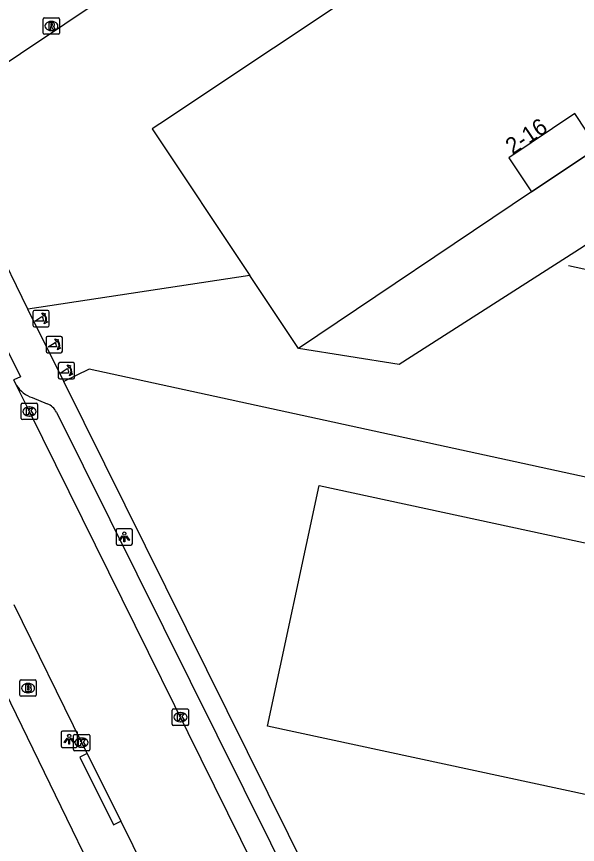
# Model space of a CAD drawing. Extents: x 161354 to 161876, y 382161 to 382804.
# Drawn here: x 161440.8 to 161475, y 382456.1 to 382506.5 of the extents above; entities that cross this region are included whole.
import ezdxf

# ---------------------------------------------------------------- set-up
doc = ezdxf.new("R2010")
doc.units = 0
for name, color, linetype in [('IMGEO_Brandkraan', 7, 'Continuous'), ('IMGEO_Kolk', 7, 'Continuous'), ('IMGEO_Lichtpunt', 7, 'Continuous'), ('IMGEO_Lijnafwatering', 7, 'Continuous'), ('IMGEO_Pand', 7, 'Continuous'), ('IMGEO_Pand_nummerreeks', 7, 'Continuous'), ('IMGEO_Pand_overbouw', 7, 'Continuous'), ('IMGEO_Poller', 7, 'Continuous'), ('IMGEO_Rijbaan_lokaal_open', 7, 'Continuous'), ('IMGEO_Rioolput', 7, 'Continuous'), ('IMGEO_Voetpad_open', 7, 'Continuous')]:
    doc.layers.add(name, color=color, linetype=linetype)

msp = doc.modelspace()

# ---------------------------------------------------------------- linework, layer by layer
at = {"layer": 'IMGEO_Brandkraan'}
for p, q in [((161440.964, 382465.171), (161440.964, 382466.023)), ((161441.039, 382466.097), (161441.891, 382466.097)), ((161441.965, 382466.023), (161441.965, 382465.171)), ((161441.452, 382465.877), (161441.477, 382465.877)), ((161441.891, 382465.097), (161441.039, 382465.097)), ((161441.475, 382465.317), (161441.45, 382465.317))]:
    msp.add_line(p, q, dxfattribs=at)
for points in [[(161440.964, 382465.171), (161440.964, 382466.023)], [(161441.039, 382466.097), (161441.891, 382466.097)], [(161441.965, 382466.023), (161441.965, 382465.171)], [(161441.312, 382465.797), (161441.312, 382465.397), (161441.525, 382465.397)], [(161441.543, 382465.797), (161441.312, 382465.797)], [(161441.491, 382465.716), (161441.437, 382465.716), (161441.437, 382465.64)], [(161441.437, 382465.64), (161441.49, 382465.64)], [(161441.499, 382465.564), (161441.437, 382465.564), (161441.437, 382465.483)], [(161441.437, 382465.483), (161441.499, 382465.483)], [(161441.891, 382465.097), (161441.039, 382465.097)]]:
    msp.add_lwpolyline(points, dxfattribs=at)
for centre, radius, start, end in [((161441.041, 382466.021), 0.0765, 91.552, 178.448), ((161441.041, 382466.021), 0.0765, 91.552, 178.448), ((161441.889, 382466.021), 0.0765, 1.552, 88.448), ((161441.889, 382466.021), 0.0765, 1.552, 88.448), ((161441.492, 382465.678), 0.0379, 267.8285, 90.9355), ((161441.5, 382465.523), 0.0404, 269.8759, 90.5077), ((161441.547, 382465.652), 0.145, 59.4692, 91.5367), ((161441.572, 382465.699), 0.0922, 285.5137, 58.1501), ((161441.577, 382465.507), 0.105, 301.3115, 78.989), ((161441.041, 382465.173), 0.0765, 181.552, 268.448), ((161441.041, 382465.173), 0.0765, 181.552, 268.448), ((161441.531, 382465.648), 0.251, 268.6676, 293.5347), ((161441.889, 382465.173), 0.0765, 271.552, 358.448), ((161441.889, 382465.173), 0.0765, 271.552, 358.448)]:
    msp.add_arc(centre, radius, start, end, dxfattribs=at)
for centre, major_axis, ratio, start_param, end_param in [((161441.451, 382465.597), (-0.387, 0.002), 0.722429, 4.712389, 7.853982), ((161441.476, 382465.597), (-0.39, 0.002), 0.717154, 1.570796, 4.712389)]:
    msp.add_ellipse(centre, major_axis=major_axis, ratio=ratio, start_param=start_param, end_param=end_param, dxfattribs=at)
at = {"layer": 'IMGEO_Kolk'}
for p, q in [((161441.047, 382482.037), (161441.047, 382482.889)), ((161441.122, 382482.963), (161441.974, 382482.963)), ((161441.535, 382482.743), (161441.56, 382482.743)), ((161442.048, 382482.889), (161442.048, 382482.037)), ((161441.558, 382482.183), (161441.533, 382482.183)), ((161441.974, 382481.963), (161441.122, 382481.963)), ((161450.264, 382463.396), (161450.264, 382464.248)), ((161450.339, 382464.322), (161451.191, 382464.322)), ((161450.752, 382464.102), (161450.777, 382464.102)), ((161451.265, 382464.248), (161451.265, 382463.396)), ((161450.775, 382463.542), (161450.75, 382463.542)), ((161451.191, 382463.322), (161450.339, 382463.322)), ((161444.228, 382461.848), (161444.228, 382462.7)), ((161444.303, 382462.774), (161445.155, 382462.774)), ((161444.716, 382462.554), (161444.741, 382462.554)), ((161445.229, 382462.7), (161445.229, 382461.848)), ((161444.739, 382461.994), (161444.714, 382461.994)), ((161445.155, 382461.774), (161444.303, 382461.774))]:
    msp.add_line(p, q, dxfattribs=at)
for points in [[(161441.047, 382482.037), (161441.047, 382482.889)], [(161441.122, 382482.963), (161441.974, 382482.963)], [(161441.368, 382482.663), (161441.491, 382482.663), (161441.491, 382482.512), (161441.621, 382482.663), (161441.785, 382482.663), (161441.639, 382482.512), (161441.792, 382482.263), (161441.64, 382482.263), (161441.555, 382482.427), (161441.491, 382482.36), (161441.491, 382482.263), (161441.368, 382482.263), (161441.368, 382482.663)], [(161442.048, 382482.889), (161442.048, 382482.037)], [(161441.974, 382481.963), (161441.122, 382481.963)], [(161450.264, 382463.396), (161450.264, 382464.248)], [(161450.339, 382464.322), (161451.191, 382464.322)], [(161450.585, 382464.022), (161450.708, 382464.022), (161450.708, 382463.871), (161450.838, 382464.022), (161451.002, 382464.022), (161450.856, 382463.871), (161451.009, 382463.622), (161450.857, 382463.622), (161450.772, 382463.786), (161450.708, 382463.719), (161450.708, 382463.622), (161450.585, 382463.622), (161450.585, 382464.022)], [(161451.265, 382464.248), (161451.265, 382463.396)], [(161451.191, 382463.322), (161450.339, 382463.322)], [(161444.228, 382461.848), (161444.228, 382462.7)], [(161444.303, 382462.774), (161445.155, 382462.774)], [(161444.549, 382462.474), (161444.672, 382462.474), (161444.672, 382462.323), (161444.802, 382462.474), (161444.966, 382462.474), (161444.82, 382462.323), (161444.973, 382462.074), (161444.821, 382462.074), (161444.736, 382462.238), (161444.672, 382462.171), (161444.672, 382462.074), (161444.549, 382462.074), (161444.549, 382462.474)], [(161445.229, 382462.7), (161445.229, 382461.848)], [(161445.155, 382461.774), (161444.303, 382461.774)]]:
    msp.add_lwpolyline(points, dxfattribs=at)
for centre, start, end in [((161441.124, 382482.887), 91.552, 178.448), ((161441.124, 382482.887), 91.552, 178.448), ((161441.972, 382482.887), 1.552, 88.448), ((161441.972, 382482.887), 1.552, 88.448), ((161441.124, 382482.039), 181.552, 268.448), ((161441.124, 382482.039), 181.552, 268.448), ((161441.972, 382482.039), 271.552, 358.448), ((161441.972, 382482.039), 271.552, 358.448), ((161450.341, 382464.246), 91.552, 178.448), ((161450.341, 382464.246), 91.552, 178.448), ((161451.189, 382464.246), 1.552, 88.448), ((161451.189, 382464.246), 1.552, 88.448), ((161450.341, 382463.398), 181.552, 268.448), ((161450.341, 382463.398), 181.552, 268.448), ((161451.189, 382463.398), 271.552, 358.448), ((161451.189, 382463.398), 271.552, 358.448), ((161444.305, 382462.698), 91.552, 178.448), ((161444.305, 382462.698), 91.552, 178.448), ((161445.153, 382462.698), 1.552, 88.448), ((161445.153, 382462.698), 1.552, 88.448), ((161444.305, 382461.85), 181.552, 268.448), ((161444.305, 382461.85), 181.552, 268.448), ((161445.153, 382461.85), 271.552, 358.448), ((161445.153, 382461.85), 271.552, 358.448)]:
    msp.add_arc(centre, 0.0765, start, end, dxfattribs=at)
for centre, major_axis, ratio, start_param, end_param in [((161441.534, 382482.463), (-0.387, 0.002), 0.722429, 4.712389, 7.853982), ((161441.559, 382482.463), (-0.39, 0.002), 0.717154, 1.570796, 4.712389), ((161450.751, 382463.822), (-0.387, 0.002), 0.722429, 4.712389, 7.853982), ((161450.776, 382463.822), (-0.39, 0.002), 0.717154, 1.570796, 4.712389), ((161444.715, 382462.274), (-0.387, 0.002), 0.722429, 4.712389, 7.853982), ((161444.74, 382462.274), (-0.39, 0.002), 0.717154, 1.570796, 4.712389)]:
    msp.add_ellipse(centre, major_axis=major_axis, ratio=ratio, start_param=start_param, end_param=end_param, dxfattribs=at)
at = {"layer": 'IMGEO_Lichtpunt'}
for p, q in [((161446.838, 382475.22), (161446.838, 382474.413)), ((161446.838, 382475.22), (161446.838, 382474.413)), ((161447.74, 382475.315), (161446.932, 382475.315)), ((161447.74, 382475.315), (161446.932, 382475.315)), ((161447.834, 382474.413), (161447.834, 382475.22)), ((161447.834, 382474.413), (161447.834, 382475.22)), ((161446.932, 382474.319), (161447.74, 382474.319)), ((161446.932, 382474.319), (161447.74, 382474.319)), ((161444.379, 382462.977), (161443.571, 382462.977)), ((161444.379, 382462.977), (161443.571, 382462.977)), ((161443.477, 382462.882), (161443.477, 382462.075)), ((161443.477, 382462.882), (161443.477, 382462.075)), ((161444.473, 382462.075), (161444.473, 382462.882)), ((161444.473, 382462.075), (161444.473, 382462.882)), ((161443.571, 382461.981), (161444.379, 382461.981)), ((161443.571, 382461.981), (161444.379, 382461.981))]:
    msp.add_line(p, q, dxfattribs=at)
for points in [[(161447.212, 382474.884), (161447.251, 382474.856), (161447.063, 382474.594), (161447.025, 382474.621), (161447.212, 382474.884)], [(161447.314, 382474.836), (161447.361, 382474.836), (161447.361, 382474.514), (161447.314, 382474.514), (161447.314, 382474.836)], [(161447.424, 382474.856), (161447.462, 382474.883), (161447.649, 382474.621), (161447.61, 382474.593), (161447.424, 382474.856)], [(161443.851, 382462.546), (161443.89, 382462.518), (161443.702, 382462.256), (161443.664, 382462.283), (161443.851, 382462.546)], [(161443.953, 382462.498), (161444, 382462.498), (161444, 382462.176), (161443.953, 382462.176), (161443.953, 382462.498)], [(161444.063, 382462.518), (161444.101, 382462.545), (161444.288, 382462.283), (161444.249, 382462.255), (161444.063, 382462.518)]]:
    msp.add_lwpolyline(points, dxfattribs=at)
for centre in [(161447.337, 382475.018), (161443.976, 382462.68)]:
    msp.add_circle(centre, 0.0994, dxfattribs=at)
for centre, start, end in [((161446.932, 382475.22), 90, 180), ((161446.932, 382475.22), 90, 180), ((161447.74, 382475.22), 0, 90), ((161447.74, 382475.22), 0, 90), ((161446.932, 382474.413), 180, 270), ((161446.932, 382474.413), 180, 270), ((161447.74, 382474.413), 270, 0), ((161447.74, 382474.413), 270, 360), ((161443.571, 382462.882), 90, 180), ((161443.571, 382462.882), 90, 180), ((161444.379, 382462.882), 0, 90), ((161444.379, 382462.882), 0, 90), ((161443.571, 382462.075), 180, 270), ((161443.571, 382462.075), 180, 270), ((161444.379, 382462.075), 270, 0), ((161444.379, 382462.075), 270, 360)]:
    msp.add_arc(centre, 0.0946, start, end, dxfattribs=at)
at = {"layer": 'IMGEO_Lijnafwatering'}
msp.add_lwpolyline([(161494.119, 382487.072), (161474.436, 382491.33)], dxfattribs=at)
at = {"layer": 'IMGEO_Pand'}
for points in [[(161463.38, 382509.249), (161449.506, 382500), (161449.044, 382499.691), (161455.008, 382490.746)], [(161490.393, 382508.028), (161478.402, 382500), (161475.671, 382498.172), (161472.197, 382495.844), (161457.968, 382486.306)], [(161457.968, 382486.306), (161455.008, 382490.746)], [(161485.462, 382479.04), (161497.294, 382476.49), (161493.615, 382459.469), (161478.517, 382462.719), (161477.639, 382458.64), (161456.073, 382463.283), (161459.231, 382477.951), (161480.549, 382473.354), (161481.379, 382477.176)]]:
    msp.add_lwpolyline(points, dxfattribs=at)
at = {"layer": 'IMGEO_Pand_overbouw'}
msp.add_lwpolyline([(161474.826, 382500.62), (161470.803, 382497.924), (161472.197, 382495.844), (161475.671, 382498.172), (161476.221, 382498.54)], close=True, dxfattribs=at)
at = {"layer": 'IMGEO_Poller'}
for p, q in [((161441.762, 382488.525), (161441.762, 382487.718)), ((161441.762, 382488.525), (161441.762, 382487.718)), ((161442.664, 382488.62), (161441.856, 382488.62)), ((161442.664, 382488.62), (161441.856, 382488.62)), ((161442.758, 382487.718), (161442.758, 382488.525)), ((161442.758, 382487.718), (161442.758, 382488.525)), ((161441.856, 382487.623), (161442.664, 382487.623)), ((161441.856, 382487.623), (161442.664, 382487.623)), ((161442.56, 382486.942), (161442.56, 382486.135)), ((161442.56, 382486.942), (161442.56, 382486.135)), ((161443.462, 382487.037), (161442.654, 382487.037)), ((161443.462, 382487.037), (161442.654, 382487.037)), ((161443.556, 382486.135), (161443.556, 382486.942)), ((161443.556, 382486.135), (161443.556, 382486.942)), ((161442.654, 382486.04), (161443.462, 382486.04)), ((161442.654, 382486.04), (161443.462, 382486.04)), ((161443.306, 382485.346), (161443.306, 382484.539)), ((161443.306, 382485.346), (161443.306, 382484.539)), ((161444.208, 382485.441), (161443.4, 382485.441)), ((161444.208, 382485.441), (161443.4, 382485.441)), ((161444.302, 382484.539), (161444.302, 382485.346)), ((161444.302, 382484.539), (161444.302, 382485.346)), ((161443.4, 382484.444), (161444.208, 382484.444)), ((161443.4, 382484.444), (161444.208, 382484.444))]:
    msp.add_line(p, q, dxfattribs=at)
for points in [[(161442.397, 382487.976), (161441.884, 382487.976), (161442.314, 382488.251)], [(161442.441, 382488.349), (161442.429, 382488.276), (161442.304, 382488.481)], [(161442.304, 382488.481), (161442.535, 382488.415), (161442.464, 382488.383)], [(161442.457, 382487.804), (161442.523, 382488.035), (161442.553, 382487.967)], [(161442.589, 382487.94), (161442.661, 382487.929), (161442.457, 382487.804)], [(161443.195, 382486.393), (161442.682, 382486.393), (161443.112, 382486.668)], [(161443.239, 382486.766), (161443.227, 382486.693), (161443.102, 382486.898)], [(161443.102, 382486.898), (161443.333, 382486.832), (161443.262, 382486.8)], [(161443.255, 382486.221), (161443.321, 382486.452), (161443.351, 382486.384)], [(161443.387, 382486.357), (161443.459, 382486.346), (161443.255, 382486.221)], [(161443.985, 382485.17), (161443.973, 382485.097), (161443.848, 382485.302)], [(161443.848, 382485.302), (161444.079, 382485.236), (161444.008, 382485.204)], [(161443.941, 382484.797), (161443.428, 382484.797), (161443.858, 382485.072)], [(161444.001, 382484.625), (161444.067, 382484.856), (161444.097, 382484.788)], [(161444.133, 382484.761), (161444.205, 382484.75), (161444.001, 382484.625)]]:
    msp.add_lwpolyline(points, dxfattribs=at)
for centre, radius, start, end in [((161441.856, 382488.525), 0.0946, 90, 180), ((161441.856, 382488.525), 0.0946, 90, 180), ((161442.069, 382488.026), 0.332, 351.3247, 42.4854), ((161442.083, 382488.036), 0.476, 351.7527, 41.1691), ((161442.083, 382488.036), 0.516, 349.3569, 42.2912), ((161442.664, 382488.525), 0.0946, 0, 90), ((161442.664, 382488.525), 0.0946, 0, 90), ((161441.856, 382487.718), 0.0946, 180, 270), ((161441.856, 382487.718), 0.0946, 180, 270), ((161442.664, 382487.718), 0.0946, 270, 0), ((161442.664, 382487.718), 0.0946, 270, 0), ((161442.654, 382486.942), 0.0946, 90, 180), ((161442.654, 382486.942), 0.0946, 90, 180), ((161442.867, 382486.443), 0.332, 351.3247, 42.4854), ((161442.881, 382486.453), 0.476, 351.7527, 41.1691), ((161442.881, 382486.453), 0.516, 349.3569, 42.2912), ((161443.462, 382486.942), 0.0946, 0, 90), ((161443.462, 382486.942), 0.0946, 0, 90), ((161442.654, 382486.135), 0.0946, 180, 270), ((161442.654, 382486.135), 0.0946, 180, 270), ((161443.462, 382486.135), 0.0946, 270, 0), ((161443.462, 382486.135), 0.0946, 270, 0), ((161443.4, 382485.346), 0.0946, 90, 180), ((161443.4, 382485.346), 0.0946, 90, 180), ((161443.627, 382484.857), 0.476, 351.7527, 41.1691), ((161443.627, 382484.857), 0.516, 349.3569, 42.2912), ((161444.208, 382485.346), 0.0946, 0, 90), ((161444.208, 382485.346), 0.0946, 0, 90), ((161443.613, 382484.847), 0.332, 351.3247, 42.4854), ((161443.4, 382484.539), 0.0946, 180, 270), ((161443.4, 382484.539), 0.0946, 180, 270), ((161444.208, 382484.539), 0.0946, 270, 0), ((161444.208, 382484.539), 0.0946, 270, 0)]:
    msp.add_arc(centre, radius, start, end, dxfattribs=at)
at = {"layer": 'IMGEO_Rijbaan_lokaal_open'}
for points in [[(161440.761, 382484.044), (161440.593, 382484.384)], [(161457.689, 382449.818), (161441.548, 382482.463), (161440.761, 382484.044)], [(161440.593, 382470.696), (161444.732, 382462.271), (161445.063, 382461.614)], [(161445.063, 382461.614), (161447.12, 382457.484)], [(161447.12, 382457.484), (161452.227, 382447.149)]]:
    msp.add_lwpolyline(points, dxfattribs=at)
at = {"layer": 'IMGEO_Rioolput'}
for p, q in [((161442.389, 382505.534), (161442.389, 382506.386)), ((161442.464, 382506.46), (161443.316, 382506.46)), ((161443.39, 382506.386), (161443.39, 382505.534)), ((161442.877, 382506.24), (161442.902, 382506.24)), ((161443.316, 382505.46), (161442.464, 382505.46)), ((161442.9, 382505.68), (161442.875, 382505.68))]:
    msp.add_line(p, q, dxfattribs=at)
for points in [[(161442.389, 382505.534), (161442.389, 382506.386)], [(161442.464, 382506.46), (161443.316, 382506.46)], [(161443.39, 382506.386), (161443.39, 382505.534)], [(161442.978, 382506.158), (161442.726, 382506.16), (161442.726, 382505.76)], [(161442.726, 382505.76), (161442.85, 382505.76), (161442.85, 382505.922), (161442.861, 382505.922)], [(161442.904, 382506.079), (161442.85, 382506.079), (161442.85, 382505.998)], [(161442.85, 382505.998), (161442.902, 382505.998)], [(161442.908, 382505.893), (161442.979, 382505.76), (161443.119, 382505.76), (161443.054, 382505.886)], [(161443.316, 382505.46), (161442.464, 382505.46)]]:
    msp.add_lwpolyline(points, dxfattribs=at)
for centre, radius, start, end in [((161442.466, 382506.384), 0.0765, 91.552, 178.448), ((161442.466, 382506.384), 0.0765, 91.552, 178.448), ((161443.314, 382506.384), 0.0765, 1.552, 88.448), ((161443.314, 382506.384), 0.0765, 1.552, 88.448), ((161442.86, 382505.869), 0.0533, 26.0293, 88.6989), ((161442.886, 382506.187), 0.19, 274.7715, 282.9687), ((161442.91, 382505.983), 0.0964, 77.0061, 93.1865), ((161442.924, 382506.04), 0.0378, 276.6634, 79.6772), ((161442.977, 382506.048), 0.109, 350.3612, 89.416), ((161442.975, 382506.048), 0.112, 277.5842, 350.9817), ((161442.959, 382505.833), 0.108, 29.5134, 73.7905), ((161442.466, 382505.536), 0.0765, 181.552, 268.448), ((161442.466, 382505.536), 0.0765, 181.552, 268.448), ((161443.314, 382505.536), 0.0765, 271.552, 358.448), ((161443.314, 382505.536), 0.0765, 271.552, 358.448)]:
    msp.add_arc(centre, radius, start, end, dxfattribs=at)
for centre, major_axis, ratio, start_param, end_param in [((161442.876, 382505.96), (-0.387, 0.002), 0.722429, 4.712389, 7.853982), ((161442.901, 382505.96), (-0.39, 0.002), 0.717154, 1.570796, 4.712389)]:
    msp.add_ellipse(centre, major_axis=major_axis, ratio=ratio, start_param=start_param, end_param=end_param, dxfattribs=at)
at = {"layer": 'IMGEO_Voetpad_open'}
for points in [[(161435.571, 382500.672), (161489.707, 382536.855), (161494.481, 382540.047), (161497.103, 382541.796), (161500, 382543.743), (161509.001, 382549.792), (161508.958, 382549.917), (161512.013, 382551.566), (161524.1, 382548.864)], [(161545.974, 382467.342), (161539.309, 382469.447), (161522.532, 382496.667), (161520.272, 382498.234), (161512.072, 382500), (161500, 382502.6), (161494.163, 382503.857), (161491.524, 382503.311), (161486.569, 382500), (161475.341, 382492.496), (161464.119, 382485.318), (161457.968, 382486.306)], [(161441.46, 382488.708), (161437.311, 382497.143)], [(161469.314, 382406.236), (161449.97, 382444.999), (161439.035, 382467.472), (161429.86, 382485.658), (161426.786, 382491.905), (161423.96, 382492.581)], [(161455.008, 382490.746), (161441.46, 382488.708)], [(161438.28, 382489.057), (161438.635, 382489.271), (161440.999, 382484.582), (161440.593, 382484.384)], [(161443.651, 382484.283), (161441.46, 382488.708)], [(161481.379, 382477.176), (161445.186, 382485.044), (161443.651, 382484.283)], [(161460.674, 382449.996), (161457.359, 382456.669), (161443.651, 382484.283)], [(161441.717, 382483.304), (161442.639, 382482.929)], [(161443.197, 382482.422), (161457.882, 382452.893)], [(161445.063, 382461.614), (161444.616, 382461.392), (161446.673, 382457.262), (161447.12, 382457.484)]]:
    msp.add_lwpolyline(points, dxfattribs=at)
for centre, radius, start, end in [((161442.274, 382485.011), 1.795, 212.5846, 251.9315), ((161442.21, 382481.897), 1.118, 28.032, 67.4513)]:
    msp.add_arc(centre, radius, start, end, dxfattribs=at)

# ---------------------------------------------------------------- texts
at = {"layer": 'IMGEO_Pand_nummerreeks'}
msp.add_text('2-16', height=1, rotation=33.816, dxfattribs=at).set_placement((161471.031, 382498.09))

doc.saveas('drawing.dxf')
